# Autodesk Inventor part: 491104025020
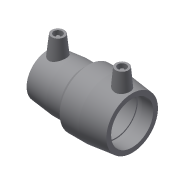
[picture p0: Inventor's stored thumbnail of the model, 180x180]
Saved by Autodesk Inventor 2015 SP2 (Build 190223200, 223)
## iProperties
Created: 2017-06
Part Number: 491104025020
Material: Generic
Description: PLASSON REDUCING COUPLER 25-20
Document SubType Name: Modeling
Designer: KIM
Mass: 54.8237 g
Surface Area: 155.252 cm^2
Volume: 54.8237 cm^3
Density: 1 g/cm^3
Appearance: Default
Author: KIM
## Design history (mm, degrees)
derived "491104.ipt"
feature "Solid1::491104.ipt"
tag "TaggingFeature1"
body "Solid1"
other parameters: "d0" = 71, "d2" = 36, "d3" = 35, "d4" = 21, "d5" = 32.4, "d8" = 168 deg, "d10" = 14, "d11" = 4.66667, "d13" = 71, "d14" = 17.6296, "d15" = 35, "d19" = 1.75, "d20" = 168 deg, "d22" = 108.92847, "d25" = 135 deg, "d29" = 39, "d30" = 15, "d31" = 24.85, "d34" = 6 deg, "d35" = 15, "d38" = 28, "d39" = 5 deg, "d41" = 4, "d42" = 14, "d43" = 0, "d45" = 4, "d46" = 14, "d47" = 0, "d48" = 36, "d50" = 36, "d52" = 18, "d53" = 14, "d54" = 4.66667, "d55" = 168 deg, "d56" = 21, "d57" = 35, "d58" = 32.4, "d59" = 0.91, "d60" = 135 deg, "d61" = 39, "d62" = 15, "d64" = 4, "d66" = 5 deg, "d67" = 14, "d68" = 0, "d69" = 24.85, "d70" = 36, "d71" = 36, "d73" = 33.84, "d76" = 1.75, "d77" = 168 deg, "d79" = 1.75, "d80" = 35, "d81" = 18, "d82" = 33.84, "d83" = 120 deg, "d88" = 15, "d89" = 28, "d90" = 5 deg, "d92" = 4, "d93" = 14, "d94" = 0, "d95" = 3, "d96" = 0, "d97" = 3, "d98" = 0, "d99" = 10.15, "d100" = 2.5375, "d101" = 32.8248, "d102" = 20 deg, "d103" = 10.15, "d104" = 2.5375, "d105" = 32.8248, "d106" = 3.60705, "d107" = 3, "d108" = 0, "d109" = 3, "d110" = 0, "L_" = 71, "L_2" = 35, "D_1" = 36, "A_1" = 39, "d_2" = 12, "L_1" = 35, "A_" = 39, "D_" = 36
